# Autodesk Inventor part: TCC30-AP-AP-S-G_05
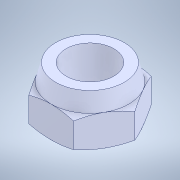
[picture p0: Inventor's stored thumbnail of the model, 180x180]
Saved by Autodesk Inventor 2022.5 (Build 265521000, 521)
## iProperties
Created: 2023-09
Part Number: TCC30-AP-AP-S-G_05
Material: 一般
Document SubType Name: Modeling
Designer: ImaoCorp
Density: 1 g/cm^3
Appearance: 既定
Author: ImaoCorp
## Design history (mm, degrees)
feature "TCC30-AP-AP-S-G_05"
node "ソリッド1"
